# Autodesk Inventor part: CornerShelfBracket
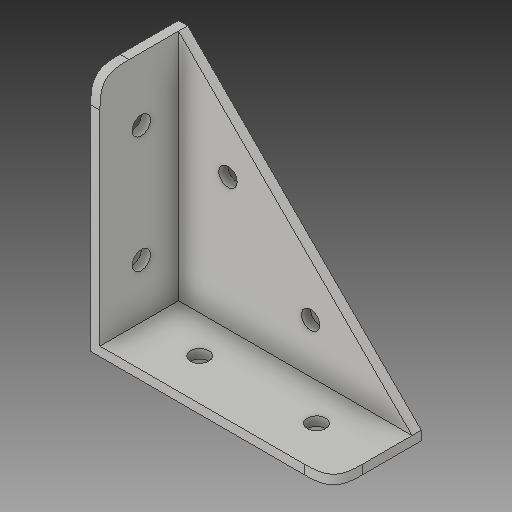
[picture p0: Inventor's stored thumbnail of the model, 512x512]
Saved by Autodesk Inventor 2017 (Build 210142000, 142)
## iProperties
Created: 2017-05
Part Number: CornerShelfBracket
Material: Generic
Document SubType Name: Modeling
Designer: Savy
Density: 1 g/cm^3
Appearance: Default
Author: Savy
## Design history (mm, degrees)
feature "Base1"
body "Solid1"
